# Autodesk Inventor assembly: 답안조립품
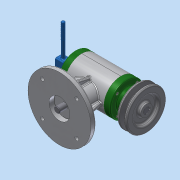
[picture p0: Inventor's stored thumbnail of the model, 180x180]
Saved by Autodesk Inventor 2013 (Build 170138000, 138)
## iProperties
Created: 2017-02
Part Number: 답안조립품
Document SubType Name: Assembly
Designer: dgall
Mass: 1814.1 g
Surface Area: 1453.46 cm^2
Volume: 463.015 cm^3
Density: 3.91801 g/cm^3
Author: dgall
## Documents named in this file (16)
- C:\Users\dgall\Desktop\370207V1027\답안조립품.iam
- C:\Users\dgall\Desktop\370207V1027\본체.ipt
- C:\Users\dgall\Desktop\370207V1027\V벨트풀리.ipt
- C:\Users\dgall\Desktop\370207V1027\가변스프링.ipt
- C:\Users\dgall\Desktop\370207V1027\뒤커버.ipt
- C:\Users\dgall\Desktop\370207V1027\레버.ipt
- C:\Users\dgall\Desktop\370207V1027\멈춤나사 M3x8.ipt
- C:\Users\dgall\Desktop\370207V1027\베어링 6201.ipt
- C:\Users\dgall\Desktop\370207V1027\베어링 6202.ipt
- C:\Users\dgall\Desktop\370207V1027\본체상부커버.ipt
- C:\Users\dgall\Desktop\370207V1027\볼트 M3x0.5x8.ipt
- C:\Users\dgall\Desktop\370207V1027\슬라이드.ipt
- C:\Users\dgall\Desktop\370207V1027\앞커버.ipt
- C:\Users\dgall\Desktop\370207V1027\오일실 12 22 7.ipt
- C:\Users\dgall\Desktop\370207V1027\키 4 x 4 x 18.ipt
- C:\Users\dgall\Desktop\370207V1027\편심축.ipt
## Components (2 placed, 2 different names)
1. V벨트풀리:1
2. 가변스프링:1
